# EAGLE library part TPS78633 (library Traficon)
ULTRALOW-NOISE, HIGH-PSRR, FAST, RF, 1.5-A LOW-DROPOUT LINEAR REGULATORS
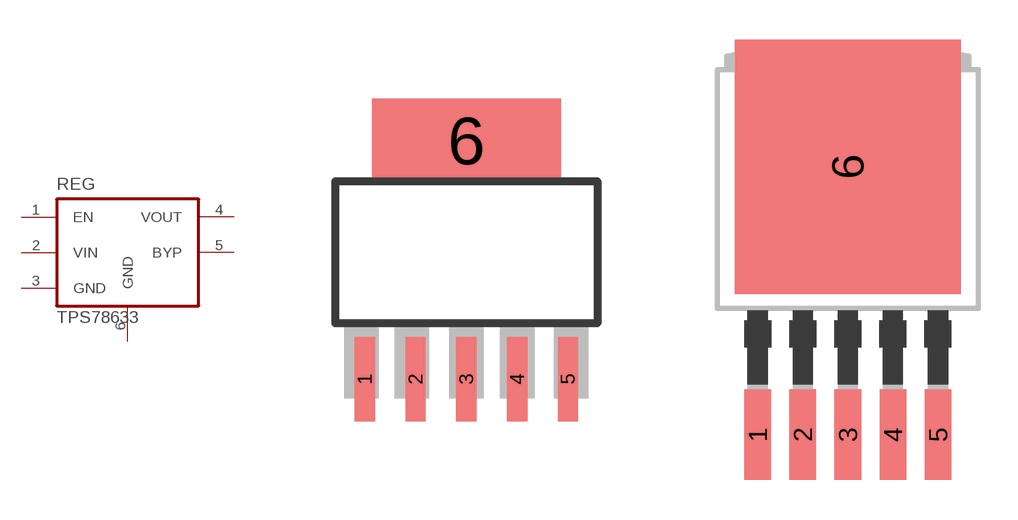
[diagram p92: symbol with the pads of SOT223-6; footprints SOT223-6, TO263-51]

Designator prefix REG

## TPS78633DCQ  [SOT223-6]
1  EN
2  VIN
3  GND
4  VOUT
5  BYP
6  GND

## TPS78633KTT  [TO263-51]
Pads as for SOT223-6

## Footprint SOT223-6 (pad centres in mm)
smd 0.508 x 2.108: 1 -2.54,-2.54; 2 -1.27,-2.54; 3 0,-2.54; 4 1.27,-2.54; 5 2.54,-2.54
smd 4.724 x 2.108: 6 0,3.429

## Footprint TO263-51 (pad centres in mm)
Transistor Outline Package P-TO263-5-1 SIEMENS TLE4270
smd 1 x 3.4: 1 -3.4,-6.6; 2 -1.7,-6.6; 3 0,-6.6; 4 1.7,-6.6; 5 3.4,-6.6
smd 8.5 x 9.6: 6 0,3.5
